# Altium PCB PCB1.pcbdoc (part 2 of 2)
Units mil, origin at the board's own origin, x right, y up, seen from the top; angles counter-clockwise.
Board outline 2362.2 x 2361.9 mil, 2 copper layers (Top Layer, Bottom Layer), stack 62.2 mil thick; 39 components, 38 nets, 262 pads, 86 vias.
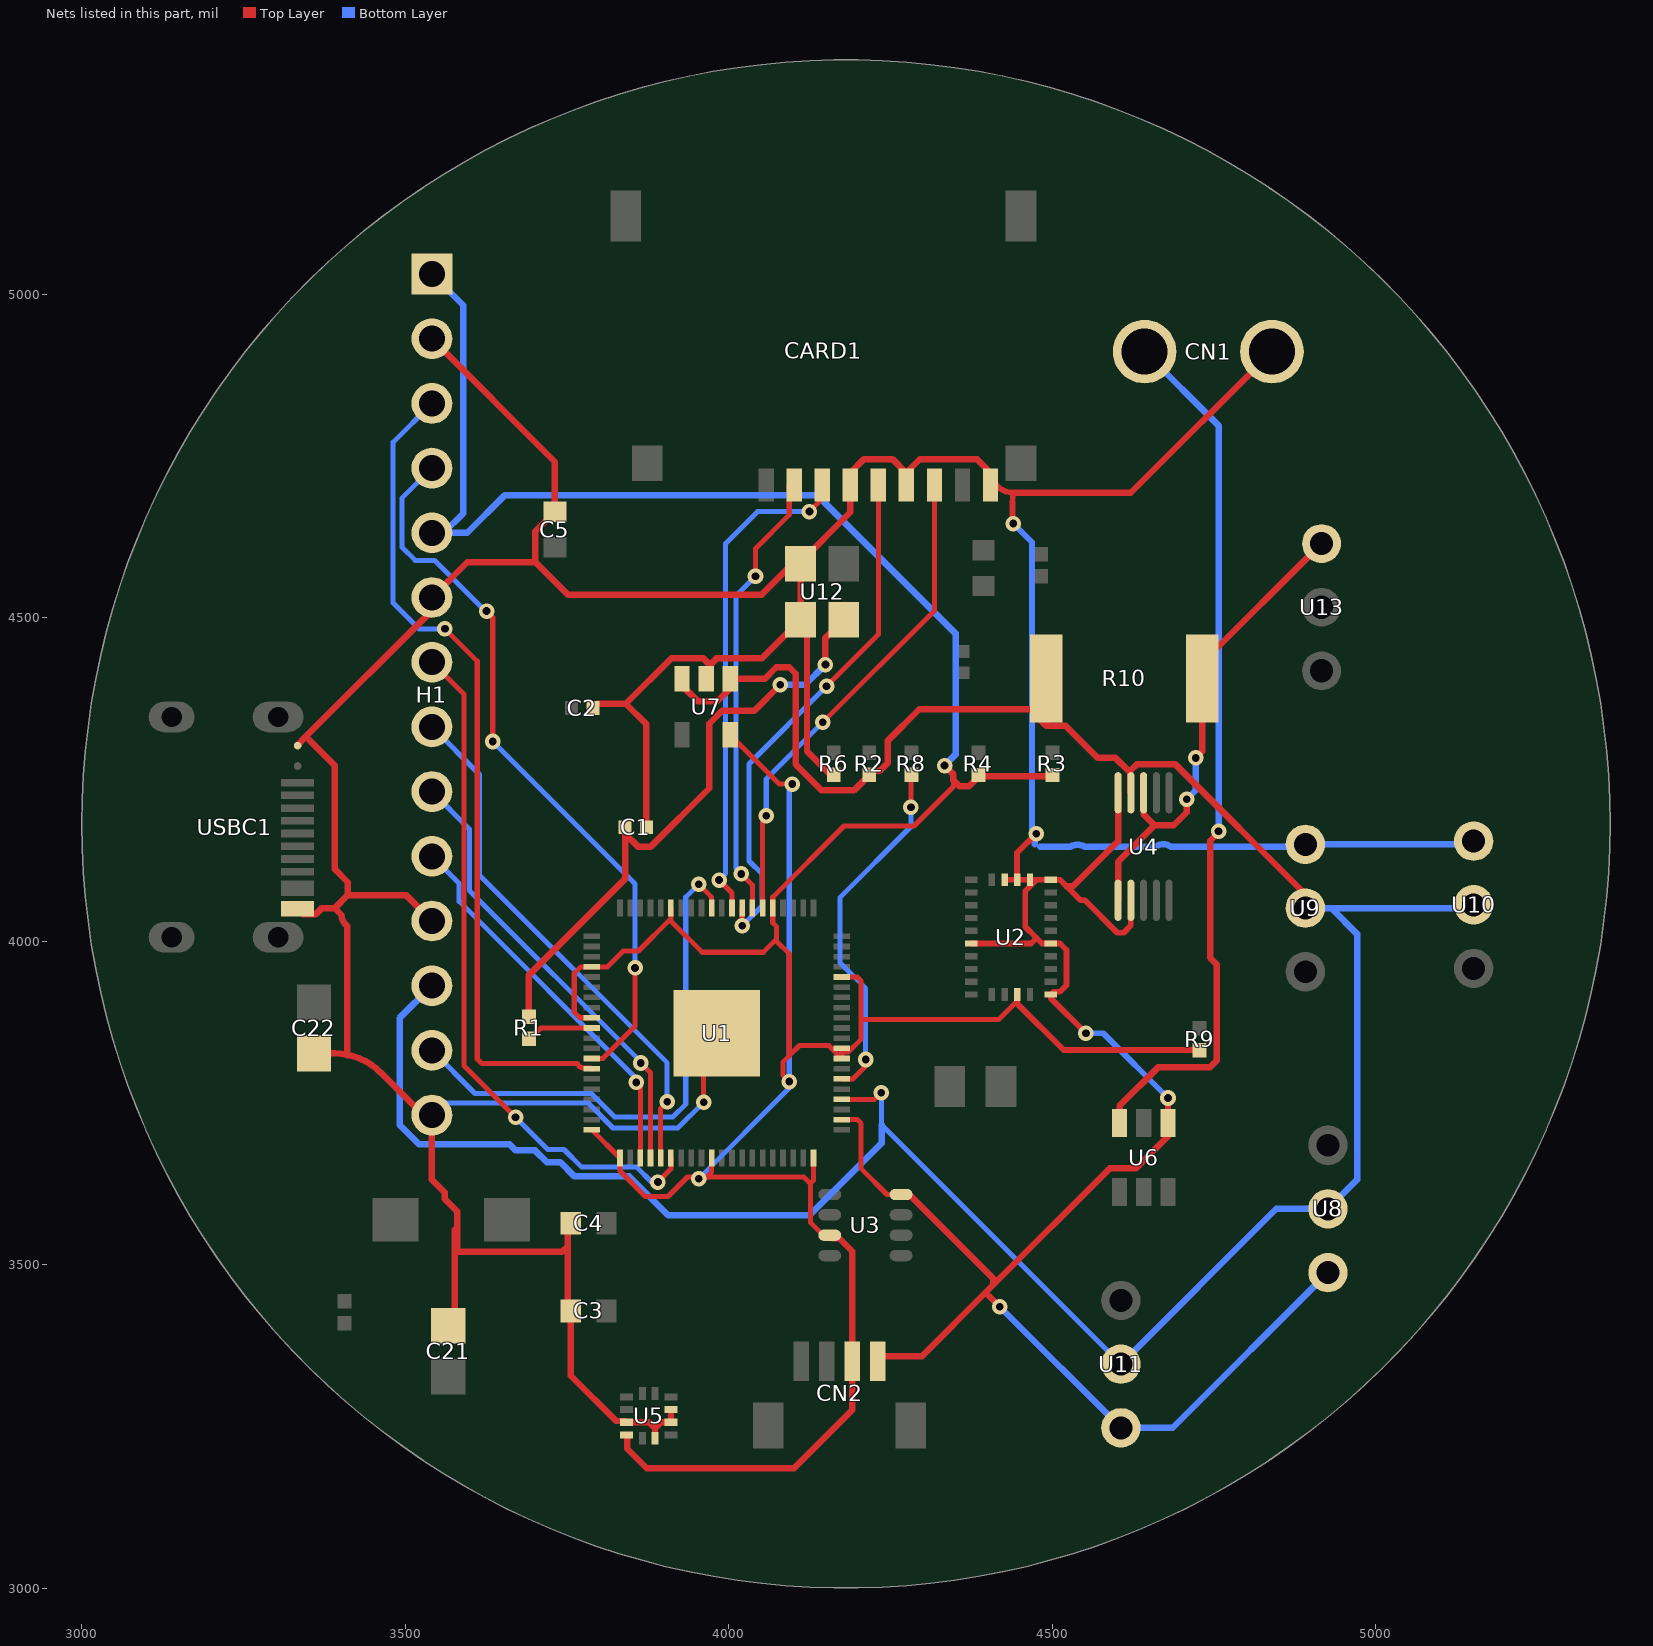
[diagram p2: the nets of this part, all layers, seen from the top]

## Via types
v1: diameter 24, hole 12, Top Layer to Bottom Layer, 86 vias

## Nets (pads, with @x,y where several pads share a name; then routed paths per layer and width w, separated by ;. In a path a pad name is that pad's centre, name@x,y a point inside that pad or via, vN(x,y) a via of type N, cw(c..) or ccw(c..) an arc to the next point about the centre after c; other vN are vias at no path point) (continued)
$1N398: H1.3 U1.34 | length 1298.7
  Top Layer w7.8: v1(3561.1,4482.7) 3611.1,4432.7 3611.1,3817.9 3618.5,3810.5 3765.8,3810.5 ; 3765.79,3810.47 ccw(c3775,3814.1) 3775,3804.2 3786.6,3804.2 U1.34@3788.1,3802.7
  Bottom Layer w7.8: H1.3@3541.1,4831.1 3481.1,4771.1 3481.1,4522.7 3521.1,4482.7 v1(3561.1,4482.7)
$1N399: H1.4 U1.33 | length 1137.2
  Top Layer w7.8: v1(3625.5,4510.1) 3635.1,4500.5 v1(3635.1,4308.5) ; U1.33@3788.1,3818.5 3805.1,3818.5 3855.1,3868.5 v1(3855.1,3958.5)
  Bottom Layer w7.8: H1.4@3541.1,4731.1 3495.1,4685.1 3495.1,4608.5 3515.1,4588.5 3545.1,4588.5 3623.5,4510.1 v1(3625.5,4510.1) ; v1(3635.1,4308.5) 3855.1,4088.5 v1(3855.1,3958.5)
$1N400: H1.7 U1.46 | length 1063.8
  Top Layer w7.8: H1.7@3541.1,4431.1 3590.4,4381.8 3590.4,3807.6 v1(3670.4,3727.6) ; v1(3890.4,3627.6) 3910.4,3647.6 U1.46@3910.4,3664.6
  Bottom Layer w7.8: v1(3670.4,3727.6) 3720.1,3678 3745.1,3678 3772,3651.1 3857,3651.1 3880.4,3627.6 v1(3890.4,3627.6)
$1N401: H1.8 U1.45 | length 821.3
  Top Layer w7.8: U1.45@3894.7,3664.6 3894.7,3741.6 v1(3904.7,3751.6)
  Bottom Layer w7.8: H1.8@3541.1,4331.1 3614.7,4257.5 3614.7,4101.8 3904.7,3811.8 v1(3904.7,3751.6)
$1N402: H1.9 U1.44 | length 706.4
  Top Layer w7.8: v1(3863.9,3811.6) 3878.9,3796.6 U1.44@3878.9,3664.6
  Bottom Layer w7.8: H1.9@3541.1,4231.1 3598.9,4173.3 3598.9,4078.3 3863.9,3813.3 v1(3863.9,3811.6)
$1N403: H1.10 U1.43 | length 599.9
  Top Layer w7.8: v1(3857,3781.6) 3863.2,3775.5 U1.43@3863.2,3664.6
  Bottom Layer w7.8: H1.10@3541.1,4131.1 3583.2,4089 3583.2,4061.4 3857,3787.5 v1(3857,3781.6)
$1N404: H1.13 U1.11 | length 836.8
  Top Layer w7.8: v1(3953.4,4088) 3973.4,4068 U1.11@3973.4,4051.1
  Bottom Layer w7.8: H1.13@3541.1,3831.1 3607.7,3764.6 3787.2,3764.6 3823.7,3728 3913.4,3728 3933.4,3748 3933.4,4068 v1(3953.4,4088)
$1N405: CARD1.5 U1.8 | length 820.4
  Top Layer w7.8: v1(4020.7,4023.9) U1.8@4020.7,4051.1 ; v1(4151.1,4393.9) 4231.1,4473.9 CARD1.5@4231.1,4713.4
  Bottom Layer w7.8: v1(4020.7,4023.9) 4051.1,4054.4 4051.1,4103.9 4031.1,4123.9 4031.1,4273.9 v1(4151.1,4393.9)
$1N406: CARD1.3 U1.9 | length 783.6
  Top Layer w7.8: v1(3984.9,4094.3) 4004.9,4074.3 U1.9@4004.9,4051.1 ; v1(4124.5,4663.9) 4144.5,4683.9 CARD1.3@4144.5,4713.4
  Bottom Layer w7.8: v1(3984.9,4094.3) 3994.9,4104.3 3994.9,4614.3 4044.5,4663.9 v1(4124.5,4663.9)
$1N409: CARD1.2 U1.7 | length 710
  Top Layer w7.8: v1(4019.3,4103.9) 4036.4,4086.7 U1.7@4036.4,4051.1 ; v1(4041.2,4563.9) 4041.2,4606.6 4093.4,4658.8 4093.4,4705.6 CARD1.2@4101.2,4713.4
  Bottom Layer w7.8: v1(4019.3,4103.9) 4011.2,4111.9 4011.2,4533.9 v1(4041.2,4563.9)
$1N410: CARD1.7 U1.6 | length 772.3
  Top Layer w7.8: U1.6@4052.2,4051.1 4052.2,4188.3 v1(4057.8,4193.9) ; v1(4145.3,4338.2) 4317.8,4510.6 CARD1.7@4317.8,4713.4
  Bottom Layer w7.8: v1(4057.8,4193.9) 4057.8,4250.6 v1(4145.3,4338.2)
$1N413: R8.1 U1.66 | length 557.5
  Top Layer w7.8: U1.66@4174.5,3787 4191.5,3787 4211.5,3807 v1(4211.5,3817) ; v1(4281.5,4207) 4281.5,4256.2 R8.1@4282.2,4256.8
  Bottom Layer w7.8: v1(4211.5,3817) 4211.5,3927 4171.5,3967 4171.5,4067 4281.5,4177 v1(4281.5,4207)
$1N418: CN1.2 U6.3 | length 1358.4
  Top Layer w10: U6.3@4604,3718.6 4604,3745.3 4664,3805.3 4744,3805.3 4754,3815.3 4754,3964 4744,3974 4744,4155.3 4757,4168.3 v1(4757,4169.9)
  Bottom Layer w10: CN1.2@4642.7,4911.1 4757,4796.8 v1(4757,4169.9)
$1N424: R1.1 U1.30 | length 103.9
  Top Layer w7.8: R1.1@3691.1,3849.1 3704.1,3862.1 3705.8,3862.1 3709.4,3865.7 U1.30@3788.1,3865.7
$1N425: C1.1 R1.2 U12.1 | length 928.8
  Top Layer w10: R1.2@3691.1,3883.1 3691.1,3947.6 3839.6,4096.1 C1.1@3839.6,4166.1 ; C1.1@3839.6,4176.1 C1.1@3839.6,4166.1 ; v1(4079.6,4396.1) 4039.6,4356.1 3989.6,4356.1 3969.6,4336.1 3969.6,4236.1 3879.6,4146.1 3859.6,4146.1 C1.1@3839.6,4166.1 ; v1(4149.3,4427.4) 4149.3,4468.5 U12.1@4177.7,4496.9
  Bottom Layer w10: v1(4079.6,4396.1) 4117.9,4396.1 v1(4149.3,4427.4)
$1N426: C1.2 C2.2 C3.2 C4.2 C5.2 C21.2 C22.2 CARD1.4 CARD1.6 CARD1.9 CN1.1 CN2.1 H1.2 H1.6 H1.11 H1.14 R6.2 U1.62 U1.81 U2.6 U2.10 U2.15 U2.16 U2.17 U2.18 U2.25 U3.5 U4.2 U4.10 U5.2 U5.3 U5.9 U5.12 U6.1 U7.2 U8.3 U9.3 U10.3 U11.3 U12.3 U12.4 USBC1.A1B12 USBC1.B1A12 | length 9984
  Top Layer w7.8: v1(3961.1,3751.1) 3961.1,3837.6 U1.81@3981.3,3857.8 ; U1.62@4174.5,3724 4199,3724 4204.6,3718.3 4204.6,3648.3 4244.6,3608.3 U3.5@4266.2,3608.3
  Top Layer w8.9: U2.25@4374.6,3996.3 4467.2,3996.3 4475.6,4004.7 ; CARD1.9@4409.9,4708.4 CARD1.9@4415.3,4703 ; CARD1.9@4415.19,4702.99 ccw(c4438.1,4725.9) 4438.1,4693.5 ; U2.18@4427.25,4094.75 ccw(c4428.1,4095.6) U2.18@4428.1,4094.4 ; U2.18@4428.1,4094.3 4440.1,4094.7 ; 4438.3,4679.5 4438.3,4646.8 v1(4439.7,4645.4) ; 4438.7,4684.2 4438.7,4692.8 ; U2.17@4445.5,4100 4445.5,4136.4 v1(4475.1,4166) ; U2.17@4445.9,4094.7 U2.16@4465.6,4094.7 4475.6,4094.7 ; v1(4551.9,3857.5) 4497.6,3911.8 U2.6@4497.6,3917.5 4501.9,3921.8 4511.9,3921.8 4521.9,3931.8 4521.9,3986.3 4511.9,3996.3 U2.10@4497.6,3996.3 4484,3996.3 4475.6,4004.7 ; U4.2@4621.4,4063 4621.4,4024.2 4610.3,4013 4600.3,4013 4550.3,4063 4543.6,4063 4521.9,4084.7 4511.9,4094.7 U2.15@4497.6,4094.7 4475.6,4094.7 ; U6.1@4678.8,3718.6 v1(4678.8,3757.5) ; 4475.6,4004.7 4458.3,4022.1 4458.3,4077.3 4475.6,4094.7
  Top Layer w9.9: C3.2@3755.9,3428.3 3755.9,3328.3 3825.9,3258.3 3839.6,3258.3 U5.9@3841.7,3256.3 3876.5,3256.3 3885.9,3246.8 ; U5.12@3885.9,3231.7 3885.9,3246.8 ; U5.3@3910.6,3275.9 U5.2@3910.6,3256.3 3895.4,3256.3 3885.9,3246.8 ; CN2.1@4230.2,3350.8 4238,3358.6 4298.8,3358.6 4398.8,3458.6 4408.8,3468.6 4588.8,3648.6 4628.8,3648.6 4678.8,3698.6 U6.1@4678.8,3718.6
  Top Layer w10: USBC1.B1A12@3333.5,4050.1 3342.5,4041.1 3361.1,4041.1 3371.1,4051.1 3390.8,4051.1 ; USBC1.A1B12@3333.5,4302.1 3341.1,4311.1 3541.1,4511.1 H1.6@3541.1,4531.1 3595.7,4585.7 3701.1,4585.7 ; 3351.1,4311.1 3391.1,4271.1 3391.1,4111.1 3411.1,4091.1 3411.1,4071.1 ; C22.2@3368,3826.4 3390.8,3826.4 cw(c3390.8,3726.4) 3410.22,3824.5 cw(c3390.8,3726.4) 3461.51,3797.11 H1.14@3536,3722.6 ; 3390.5,4051.4 3390.8,4051.1 ; 3410.26,4023.23 cw(c3424.1,4041.6) 3401.11,4040.8 3390.8,4051.1 ; 3410.3,3823.6 3410.3,3824.5 3410.3,4023.2 ; H1.14@3541.1,3748.4 3541.1,3631.1 3560.7,3611.5 3560.7,3601.5 3579.9,3582.3 3579.9,3519.5 3742.1,3519.5 3751.1,3528.5 ; H1.11@3541.1,4031.1 3501.1,4071.1 3411.1,4071.1 ; H1.2@3541.1,4931.1 3731.1,4741.1 C5.2@3731.1,4663.7 3701.1,4633.7 3701.1,4585.7 ; C21.2@3566.1,3405.5 3576.1,3415.5 3576.1,3554.1 ; C3.2@3755.9,3428.3 3751.1,3433.1 3751.1,3528.5 ; C4.2@3755.9,3563.9 3751.1,3561.1 3751.1,3528.5 ; C2.2@3790,4360.2 3796.6,4366.9 3840.8,4366.9 ; C1.2@3872.6,4176.1 3872.6,4335 3840.8,4366.9 ; U7.2@3964.9,4405.2 3970.8,4411.1 3970.8,4426.9 ; U12.3@4100.8,4585.7 4050.8,4535.7 3751.1,4535.7 3701.1,4585.7 ; R6.2@4162.3,4256.8 4157.4,4256.8 4120.8,4293.5 4120.8,4493.5 U12.4@4110.8,4503.5 ; U3.5@4266.2,3608.3 4279,3608.3 4408.8,3478.6 4408.8,3468.6 ; CARD1.6@4274.4,4713.4 CARD1.6@4274.4,4723.4 ; 4398.8,3458.6 4398.8,3455 v1(4418.8,3435) ; CARD1.9@4404.4,4713.4 4404.4,4724 4383.7,4744.8 4295.2,4744.8 4274.4,4724 CARD1.6@4274.4,4723.4 ; 4438.7,4693 4621.4,4693 CN1.1@4839.5,4911.1 ; 4521.9,4084.7 4531.9,4084.7 4601.9,4154.7 U4.10@4601.9,4229 ; 3390.8,4051.1 3391.1,4051.1 3411.1,4071.1 ; 3840.8,4366.9 3910.8,4436.9 3960.8,4436.9 3970.8,4426.9 ; 3970.8,4426.9 3980.8,4436.9 4050.8,4436.9 U12.4@4110.8,4496.9 U12.4@4110.8,4503.5 ; U12.4@4110.8,4503.5 U12.3@4110.8,4583.5 4110.8,4585.7 4187.8,4662.8 4187.8,4724 4208.9,4745.1 4252.8,4745.1 CARD1.6@4274.4,4723.4
  Bottom Layer w7.8: H1.14@3541.1,3731.1 3559.6,3749.6 3782.7,3749.6 3821.1,3711.1 3921.1,3711.1 v1(3961.1,3751.1)
  Bottom Layer w8.9: v1(4439.7,4645.4) 4468.6,4616.5 4468.6,4172.6 v1(4475.1,4166) ; v1(4551.9,3857.5) 4578.8,3857.5 v1(4678.8,3757.5)
  Bottom Layer w10: v1(4418.8,3435) U11.3@4606.1,3247.7 4686.1,3247.7 U8.3@4926.1,3487.7 ; 4472.9,4149.6 4472.9,4163.8 v1(4475.1,4166) ; 4481,4145.5 4527.2,4145.5 ; 4527.22,4145.56 cw(c4539,4125.8) 4550.78,4145.56 ; 4550.7,4145.5 4658.5,4145.5 ; 4658.54,4145.5 cw(c4671.5,4126.5) 4684.46,4145.5 ; 4684.4,4145.5 U9.3@4887.3,4145.5 ; U9.3@4891.1,4149.5 5146.1,4149.5 U10.3@5151.1,4154.5
$1N433: CN2.2 H1.1 H1.5 R3.2 R4.2 R9.2 U1.5 U1.15 U1.24 U1.29 U1.40 U1.41 U1.50 U1.60 U1.68 U1.69 U1.76 U2.4 U3.2 U5.10 U7.5 | length 5859.6
  Top Layer w7.8: U1.40@3788.1,3708.2 U1.41@3831.7,3664.6 3831.7,3644.6 3871,3605.4 3906,3605.4 3936,3635.4 3966,3635.4 ; U1.29@3788.1,3881.5 3769.8,3881.5 3761.1,3890.2 3761.1,3950.2 3771.1,3960.2 U1.24@3788.1,3960.2 3812.4,3960.2 3836.8,3984.6 3860.4,3984.6 3909.6,4033.7 ; U1.15@3910.4,4051.1 3910.4,4034.6 3909.6,4033.7 ; v1(3953.4,3632.8) 3963.4,3632.8 3966,3635.4 ; U1.50@3973.4,3664.6 3973.4,3642.8 3966,3635.4 ; U7.5@4002.3,4318.6 4078.1,4242.8 v1(4098.1,4242.8) ; v1(4093.4,3782.8) 4083.4,3792.8 4083.4,3812.8 4093.4,3822.8 ; U1.60@4130.9,3664.6 4130.9,3630.3 4126,3625.4 ; U3.2@4156,3545.4 4146,3545.4 4126,3565.4 4126,3625.4 ; U1.69@4174.5,3834.2 4174.5,3828.5 ; U1.76@4174.5,3944.5 4198.5,3944.5 4204.5,3938.5 4204.5,3878.5 ; 4347.1,4248.8 4347.1,4238.8 4286.3,4178 4177.9,4178 4067.9,4068 U1.5@4067.9,4051.1 4067.9,4028.3 4073.4,4022.8 4073.4,4002.8 ; 4445.9,3907.5 4416.9,3878.5 4204.5,3878.5 ; 3909.6,4033.7 3909.6,4031.9 3958.7,3982.8 4053.4,3982.8 4073.4,4002.8 ; 3966,3635.4 4116,3635.4 4126,3625.4 ; 4073.4,4002.8 4073.4,4000.3 4093.4,3980.3 4093.4,3822.8 ; 4093.4,3822.8 4109.1,3838.5 4154.5,3838.5 U1.68@4174.5,3818.5 4174.5,3828.5 ; 4174.5,3828.5 4184.5,3828.5 4204.5,3848.5 4204.5,3878.5
  Top Layer w8.9: U2.4@4445.9,3917.5 4445.9,3907.5 4445.9,3903.3 4517.7,3831.5 R9.2@4727.5,3831.5
  Top Layer w9.9: U5.10@3841.7,3236.6 3842.9,3235.3 3842.9,3215.3 3872.9,3185.3 4100.8,3185.3 4190.8,3275.3 CN2.2@4190.8,3350.8
  Top Layer w10: U3.2@4156,3545.4 4160.5,3540.8 4170.8,3540.8 4190.8,3520.8 CN2.2@4190.8,3350.8 ; v1(4333.4,4271.3) 4347.1,4257.6 4347.1,4248.8 4356.8,4239.1 4371,4239.1 4386.8,4254.9 R3.2@4495.8,4254.9 ; R3.2@4495.8,4255 ccw(c4495.8,4261) R3.2@4500.04,4256.76
  Bottom Layer w7.8: v1(3953.4,3632.8) 4093.4,3772.8 v1(4093.4,3782.8) 4093.4,4238.1 v1(4098.1,4242.8)
  Bottom Layer w10: H1.5@3541.1,4631.1 H1.5@3559.4,4631.1 ; H1.1@3541.1,5031.1 3589.4,4982.8 3589.4,4661.1 H1.5@3559.4,4631.1 ; v1(4333.4,4271.3) 4350.5,4288.3 4350.5,4475.5 4137.1,4688.8 3653.4,4688.8 3595.7,4631.1 H1.5@3559.4,4631.1
$1N435: R10.1 U4.1 U4.8 U13.1 | length 756.3
  Top Layer w10: U4.1@4601.7,4063 4601.7,4123 4657.9,4179.2 ; U4.8@4641.1,4229.2 4641.1,4196 4657.9,4179.2 ; v1(4707.9,4219.2) 4707.9,4199.2 4687.9,4179.2 4657.9,4179.2 ; v1(4721.8,4283.1) 4731.8,4293.1 R10.1@4731.8,4406.1 4731.8,4430.2 U13.1@4916.1,4614.5
  Bottom Layer w10: v1(4707.9,4219.2) 4721.8,4233.1 v1(4721.8,4283.1)
$1N436: H1.12 R2.2 R10.2 U1.64 U4.9 U7.1 U7.3 U8.2 U9.2 U10.2 U11.2 | length 4435.6
  Top Layer w7.8: U1.64@4174.5,3755.5 4225.5,3755.5 v1(4235.5,3765.5)
  Top Layer w10: U7.3@3927.5,4405.2 3932.3,4400.5 3932.3,4390.6 3952.3,4370.6 3982.3,4370.6 4002.3,4390.6 U7.1@4002.3,4405.2 4055.6,4405.2 4073.5,4423.1 4093.5,4423.1 4103.5,4413.1 4103.5,4273.1 4143.6,4232.9 4193.3,4232.9 4223.5,4263.1 4233.5,4263.1 4245.9,4275.5 4245.9,4309.9 4294.5,4358.5 4465,4358.5 4490.4,4333.1 ; R10.2@4490.4,4406.1 4490.4,4333.1 ; U4.9@4621.4,4229.2 4620.4,4230.2 4620.4,4263.1 ; U9.2@4891.1,4051.1 4891.1,4072.3 4690.4,4273.1 4630.4,4273.1 4620.4,4263.1 ; 4490.4,4333.1 4520.1,4333.1 4570.1,4283.1 4597.6,4283.1 4617.6,4263.1 4620.4,4263.1
  Bottom Layer w7.8: v1(4235.5,3765.5) 4236.1,3764.9 4236.1,3716.1 U11.2@4606.1,3346.1
  Bottom Layer w10: H1.12@3541.1,3931.1 3491.1,3881.1 3491.1,3716.1 3521.1,3686.1 3661.1,3686.1 3670.7,3676.5 3700.5,3676.5 3718.9,3658.1 3739.7,3658.1 3761.6,3636.2 3846,3636.2 3906.1,3576.1 4124.8,3576.1 4236.1,3687.4 4236.1,3716.1 ; U11.2@4606.1,3346.1 4846.1,3586.1 U8.2@4926.1,3586.1 4971.1,3631.2 4971.1,4011.1 4931.1,4051.1 ; U9.2@4891.1,4051.1 4931.1,4051.1 ; U10.2@5151.1,4056.1 5146.1,4051.1 4931.1,4051.1
pads on no net: CARD1.1 CARD1.8 CARD1.10 CARD1.11 CARD1.12 CARD1.13 CN2.0 U1.3 U1.4 U1.12 U1.13 U1.14 U1.16 U1.17 U1.18 U1.19 U1.20 U1.21 U1.22 U1.23 U1.25 U1.26 U1.27 U1.28 U1.35 U1.36 U1.37 U1.38 U1.39 U1.42 U1.47 U1.48 U1.49 U1.52 U1.53 U1.54 U1.55 U1.56 U1.57 U1.58 U1.59 U1.70 U1.71 U1.72 U1.73 U1.74 U1.75 U2.1 U2.2 U2.3 U2.5 U2.7 U2.8 U2.9 U2.12 U2.13 U2.14 U2.21 U2.22 U2.23 U2.24 U2.26 U2.27 U2.28 U3.1 U3.6 U3.7 U3.8 U4.3 U4.6 U4.7 U5.4 U5.5 U5.6 U5.7 U5.8 U7.4 U13.3 USBC1.1 USBC1.2 USBC1.3 USBC1.4 USBC1.A5 USBC1.A7 USBC1.B5 USBC1.B6 USBC1.B7 USBC1.B8

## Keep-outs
Board Outline Layer:
  region: 3328.4,4762.6 3328,4755.8 3326.8,4749 3324.9,4742.4 3322.2,4736.1 3318.8,4730.2 3314.8,4724.6 3310.2,4719.6 3305,4715.1 3299.3,4711.2 3293.2,4708 3286.9,4705.5 3280.2,4703.8 3273.4,4702.8 3266.6,4702.6 3259.8,4703.2 3253,4704.6 3246.5,4706.7 3240.3,4709.5 3234.4,4713.1 3229,4717.2 3224.1,4722 3219.7,4727.3 3216,4733.1 3213,4739.3 3210.7,4745.7 3209.1,4752.4 3208.4,4759.2 3208.4,4766.1 3209.1,4772.9 3210.7,4779.5 3213,4786 3216,4792.2 3219.7,4797.9 3224.1,4803.2 3229,4808 3234.4,4812.2 3240.3,4815.7 3246.5,4818.6 3253,4820.7 3259.8,4822.1 3266.6,4822.6 3273.4,4822.4 3280.2,4821.5 3286.9,4819.7 3293.2,4817.2 3299.3,4814 3305,4810.2 3310.2,4805.7 3314.8,4800.6 3318.8,4795.1 3322.2,4789.1 3324.9,4782.8 3326.8,4776.2 3328,4769.5
  region: 3328.4,4762.6 3328,4755.8 3326.8,4749 3324.9,4742.4 3322.2,4736.1 3318.8,4730.2 3314.8,4724.6 3310.2,4719.6 3305,4715.1 3299.3,4711.2 3293.2,4708 3286.9,4705.5 3280.2,4703.8 3273.4,4702.8 3266.6,4702.6 3259.8,4703.2 3253,4704.6 3246.5,4706.7 3240.3,4709.5 3234.4,4713.1 3229,4717.2 3224.1,4722 3219.7,4727.3 3216,4733.1 3213,4739.3 3210.7,4745.7 3209.1,4752.4 3208.4,4759.2 3208.4,4766.1 3209.1,4772.9 3210.7,4779.5 3213,4786 3216,4792.2 3219.7,4797.9 3224.1,4803.2 3229,4808 3234.4,4812.2 3240.3,4815.7 3246.5,4818.6 3253,4820.7 3259.8,4822.1 3266.6,4822.6 3273.4,4822.4 3280.2,4821.5 3286.9,4819.7 3293.2,4817.2 3299.3,4814 3305,4810.2 3310.2,4805.7 3314.8,4800.6 3318.8,4795.1 3322.2,4789.1 3324.9,4782.8 3326.8,4776.2 3328,4769.5
  region: 5159.3,4782 5158.9,4775.1 5157.7,4768.4 5155.8,4761.8 5153.1,4755.5 5149.8,4749.5 5145.7,4744 5141.1,4738.9 5135.9,4734.4 5130.3,4730.6 5124.2,4727.4 5117.8,4724.9 5111.2,4723.1 5104.4,4722.2 5097.5,4722 5090.7,4722.5 5084,4723.9 5077.5,4726 5071.2,4728.9 5065.4,4732.4 5059.9,4736.6 5055,4741.4 5050.7,4746.7 5047,4752.4 5043.9,4758.6 5041.6,4765.1 5040.1,4771.7 5039.3,4778.5 5039.3,4785.4 5040.1,4792.2 5041.6,4798.9 5043.9,4805.3 5047,4811.5 5050.7,4817.3 5055,4822.6 5059.9,4827.4 5065.4,4831.5 5071.2,4835.1 5077.5,4837.9 5084,4840 5090.7,4841.4 5097.5,4842 5104.4,4841.8 5111.2,4840.8 5117.8,4839.1 5124.2,4836.6 5130.3,4833.4 5135.9,4829.5 5141.1,4825 5145.7,4820 5149.8,4814.4 5153.1,4808.5 5155.8,4802.2 5157.7,4795.6 5158.9,4788.8
  region: 5159.3,4782 5158.9,4775.1 5157.7,4768.4 5155.8,4761.8 5153.1,4755.5 5149.8,4749.5 5145.7,4744 5141.1,4738.9 5135.9,4734.4 5130.3,4730.6 5124.2,4727.4 5117.8,4724.9 5111.2,4723.1 5104.4,4722.2 5097.5,4722 5090.7,4722.5 5084,4723.9 5077.5,4726 5071.2,4728.9 5065.4,4732.4 5059.9,4736.6 5055,4741.4 5050.7,4746.7 5047,4752.4 5043.9,4758.6 5041.6,4765.1 5040.1,4771.7 5039.3,4778.5 5039.3,4785.4 5040.1,4792.2 5041.6,4798.9 5043.9,4805.3 5047,4811.5 5050.7,4817.3 5055,4822.6 5059.9,4827.4 5065.4,4831.5 5071.2,4835.1 5077.5,4837.9 5084,4840 5090.7,4841.4 5097.5,4842 5104.4,4841.8 5111.2,4840.8 5117.8,4839.1 5124.2,4836.6 5130.3,4833.4 5135.9,4829.5 5141.1,4825 5145.7,4820 5149.8,4814.4 5153.1,4808.5 5155.8,4802.2 5157.7,4795.6 5158.9,4788.8
  region: 3336.6,3602.4 3336.2,3595.6 3335,3588.8 3333.1,3582.3 3330.4,3575.9 3327,3570 3323,3564.4 3318.4,3559.4 3313.2,3554.9 3307.5,3551 3301.5,3547.8 3295.1,3545.3 3288.5,3543.6 3281.7,3542.6 3274.8,3542.4 3268,3543 3261.3,3544.4 3254.8,3546.5 3248.5,3549.3 3242.6,3552.9 3237.2,3557.1 3232.3,3561.8 3228,3567.1 3224.3,3572.9 3221.2,3579.1 3218.9,3585.5 3217.4,3592.2 3216.6,3599 3216.6,3605.9 3217.4,3612.7 3218.9,3619.4 3221.2,3625.8 3224.3,3632 3228,3637.7 3232.3,3643 3237.2,3647.8 3242.6,3652 3248.5,3655.5 3254.8,3658.4 3261.3,3660.5 3268,3661.9 3274.8,3662.5 3281.7,3662.3 3288.5,3661.3 3295.1,3659.5 3301.5,3657.1 3307.5,3653.9 3313.2,3650 3318.4,3645.5 3323,3640.4 3327,3634.9 3330.4,3628.9 3333.1,3622.6 3335,3616 3336.2,3609.3
  region: 3336.6,3602.4 3336.2,3595.6 3335,3588.8 3333.1,3582.3 3330.4,3575.9 3327,3570 3323,3564.4 3318.4,3559.4 3313.2,3554.9 3307.5,3551 3301.5,3547.8 3295.1,3545.3 3288.5,3543.6 3281.7,3542.6 3274.8,3542.4 3268,3543 3261.3,3544.4 3254.8,3546.5 3248.5,3549.3 3242.6,3552.9 3237.2,3557.1 3232.3,3561.8 3228,3567.1 3224.3,3572.9 3221.2,3579.1 3218.9,3585.5 3217.4,3592.2 3216.6,3599 3216.6,3605.9 3217.4,3612.7 3218.9,3619.4 3221.2,3625.8 3224.3,3632 3228,3637.7 3232.3,3643 3237.2,3647.8 3242.6,3652 3248.5,3655.5 3254.8,3658.4 3261.3,3660.5 3268,3661.9 3274.8,3662.5 3281.7,3662.3 3288.5,3661.3 3295.1,3659.5 3301.5,3657.1 3307.5,3653.9 3313.2,3650 3318.4,3645.5 3323,3640.4 3327,3634.9 3330.4,3628.9 3333.1,3622.6 3335,3616 3336.2,3609.3
  region: 5167.5,3621.8 5167.1,3614.9 5166,3608.2 5164,3601.6 5161.4,3595.3 5158,3589.3 5154,3583.8 5149.3,3578.7 5144.1,3574.2 5138.5,3570.4 5132.4,3567.2 5126,3564.7 5119.4,3562.9 5112.6,3562 5105.8,3561.8 5098.9,3562.4 5092.2,3563.7 5085.7,3565.8 5079.5,3568.7 5073.6,3572.2 5068.2,3576.4 5063.2,3581.2 5058.9,3586.5 5055.2,3592.3 5052.2,3598.4 5049.9,3604.9 5048.3,3611.5 5047.5,3618.4 5047.5,3625.2 5048.3,3632 5049.9,3638.7 5052.2,3645.2 5055.2,3651.3 5058.9,3657.1 5063.2,3662.4 5068.2,3667.2 5073.6,3671.3 5079.5,3674.9 5085.7,3677.7 5092.2,3679.9 5098.9,3681.2 5105.8,3681.8 5112.6,3681.6 5119.4,3680.6 5126,3678.9 5132.4,3676.4 5138.5,3673.2 5144.1,3669.3 5149.3,3664.8 5154,3659.8 5158,3654.2 5161.4,3648.3 5164,3642 5166,3635.4 5167.1,3628.6
  region: 5167.5,3621.8 5167.1,3614.9 5166,3608.2 5164,3601.6 5161.4,3595.3 5158,3589.3 5154,3583.8 5149.3,3578.7 5144.1,3574.2 5138.5,3570.4 5132.4,3567.2 5126,3564.7 5119.4,3562.9 5112.6,3562 5105.8,3561.8 5098.9,3562.4 5092.2,3563.7 5085.7,3565.8 5079.5,3568.7 5073.6,3572.2 5068.2,3576.4 5063.2,3581.2 5058.9,3586.5 5055.2,3592.3 5052.2,3598.4 5049.9,3604.9 5048.3,3611.5 5047.5,3618.4 5047.5,3625.2 5048.3,3632 5049.9,3638.7 5052.2,3645.2 5055.2,3651.3 5058.9,3657.1 5063.2,3662.4 5068.2,3667.2 5073.6,3671.3 5079.5,3674.9 5085.7,3677.7 5092.2,3679.9 5098.9,3681.2 5105.8,3681.8 5112.6,3681.6 5119.4,3680.6 5126,3678.9 5132.4,3676.4 5138.5,3673.2 5144.1,3669.3 5149.3,3664.8 5154,3659.8 5158,3654.2 5161.4,3648.3 5164,3642 5166,3635.4 5167.1,3628.6
  lines w0.1: 3208.4,4759.2 3209.1,4752.4 3210.7,4745.7 3213,4739.3 3216,4733.1 3219.7,4727.3 3224.1,4722 3229,4717.2 3234.4,4713.1 3240.3,4709.5 3246.5,4706.7 3253,4704.6 3259.8,4703.2 3266.6,4702.6 3273.4,4702.8 3280.2,4703.8 3286.9,4705.5 3293.2,4708 3299.3,4711.2 3305,4715.1 3310.2,4719.6 3314.8,4724.6 3318.8,4730.2 3322.2,4736.1 3324.9,4742.4 3326.8,4749 3328,4755.8 3328.4,4762.6 3328,4769.5 3326.8,4776.2 3324.9,4782.8 3322.2,4789.1 3318.8,4795.1 3314.8,4800.6 3310.2,4805.7 3305,4810.2 3299.3,4814 3293.2,4817.2 3286.9,4819.7 3280.2,4821.5 3273.4,4822.4 3266.6,4822.6 3259.8,4822.1 3253,4820.7 3246.5,4818.6 3240.3,4815.7 3234.4,4812.2 3229,4808 3224.1,4803.2 3219.7,4797.9 3216,4792.2 3213,4786 3210.7,4779.5 3209.1,4772.9 3208.4,4766.1 3208.4,4759.2 ; 3216.6,3599 3217.4,3592.2 3218.9,3585.5 3221.2,3579.1 3224.3,3572.9 3228,3567.1 3232.3,3561.8 3237.2,3557.1 3242.6,3552.9 3248.5,3549.3 3254.8,3546.5 3261.3,3544.4 3268,3543 3274.8,3542.4 3281.7,3542.6 3288.5,3543.6 3295.1,3545.3 3301.5,3547.8 3307.5,3551 3313.2,3554.9 3318.4,3559.4 3323,3564.4 3327,3570 3330.4,3575.9 3333.1,3582.3 3335,3588.8 3336.2,3595.6 3336.6,3602.4 3336.2,3609.3 3335,3616 3333.1,3622.6 3330.4,3628.9 3327,3634.9 3323,3640.4 3318.4,3645.5 3313.2,3650 3307.5,3653.9 3301.5,3657.1 3295.1,3659.5 3288.5,3661.3 3281.7,3662.3 3274.8,3662.5 3268,3661.9 3261.3,3660.5 3254.8,3658.4 3248.5,3655.5 3242.6,3652 3237.2,3647.8 3232.3,3643 3228,3637.7 3224.3,3632 3221.2,3625.8 3218.9,3619.4 3217.4,3612.7 3216.6,3605.9 3216.6,3599 ; 5039.3,4778.5 5040.1,4771.7 5041.6,4765.1 5043.9,4758.6 5047,4752.4 5050.7,4746.7 5055,4741.4 5059.9,4736.6 5065.4,4732.4 5071.2,4728.9 5077.5,4726 5084,4723.9 5090.7,4722.5 5097.5,4722 5104.4,4722.2 5111.2,4723.1 5117.8,4724.9 5124.2,4727.4 5130.3,4730.6 5135.9,4734.4 5141.1,4738.9 5145.7,4744 5149.8,4749.5 5153.1,4755.5 5155.8,4761.8 5157.7,4768.4 5158.9,4775.1 5159.3,4782 5158.9,4788.8 5157.7,4795.6 5155.8,4802.2 5153.1,4808.5 5149.8,4814.4 5145.7,4820 5141.1,4825 5135.9,4829.5 5130.3,4833.4 5124.2,4836.6 5117.8,4839.1 5111.2,4840.8 5104.4,4841.8 5097.5,4842 5090.7,4841.4 5084,4840 5077.5,4837.9 5071.2,4835.1 5065.4,4831.5 5059.9,4827.4 5055,4822.6 5050.7,4817.3 5047,4811.5 5043.9,4805.3 5041.6,4798.9 5040.1,4792.2 5039.3,4785.4 5039.3,4778.5 ; 5047.5,3618.4 5048.3,3611.5 5049.9,3604.9 5052.2,3598.4 5055.2,3592.3 5058.9,3586.5 5063.2,3581.2 5068.2,3576.4 5073.6,3572.2 5079.5,3568.7 5085.7,3565.8 5092.2,3563.7 5098.9,3562.4 5105.8,3561.8 5112.6,3562 5119.4,3562.9 5126,3564.7 5132.4,3567.2 5138.5,3570.4 5144.1,3574.2 5149.3,3578.7 5154,3583.8 5158,3589.3 5161.4,3595.3 5164,3601.6 5166,3608.2 5167.1,3614.9 5167.5,3621.8 5167.1,3628.6 5166,3635.4 5164,3642 5161.4,3648.3 5158,3654.2 5154,3659.8 5149.3,3664.8 5144.1,3669.3 5138.5,3673.2 5132.4,3676.4 5126,3678.9 5119.4,3680.6 5112.6,3681.6 5105.8,3681.8 5098.9,3681.2 5092.2,3679.9 5085.7,3677.7 5079.5,3674.9 5073.6,3671.3 5068.2,3667.2 5063.2,3662.4 5058.9,3657.1 5055.2,3651.3 5052.2,3645.2 5049.9,3638.7 5048.3,3632 5047.5,3625.2 5047.5,3618.4
  lines w10: 3000,4181.1 3000.4,4150.4 3001.6,4119.8 3003.6,4089.2 3006.4,4058.7 3009.9,4028.2 3014.3,3997.9 3019.5,3967.6 3025.4,3937.5 3032.1,3907.6 3039.6,3877.9 3047.8,3848.3 3056.9,3819 3066.6,3790 3077.2,3761.2 3088.4,3732.7 3100.5,3704.4 3113.2,3676.5 3126.7,3649 3140.8,3621.8 3155.7,3595 3171.3,3568.6 3187.5,3542.6 3204.4,3517 3222,3491.8 3240.2,3467.2 3259,3443 3278.5,3419.3 3298.6,3396.1 3319.3,3373.5 3340.5,3351.4 3362.4,3329.8 3384.7,3308.9 3407.6,3288.5 3431.1,3268.7 3455,3249.5 3479.4,3231 3504.3,3213.1 3529.7,3195.9 3555.5,3179.3 3581.7,3163.4 3608.3,3148.2 3635.4,3133.6 3662.7,3119.8 3690.5,3106.7 3718.5,3094.4 3746.9,3082.7 3775.5,3071.8 3804.5,3061.7 3833.7,3052.3 3863.1,3043.6 3892.7,3035.7 3922.6,3028.6 3952.6,3022.3 3982.7,3016.8 4013,3012 4043.4,3008.1 4073.9,3004.9 4104.5,3002.5 4135.1,3000.9 4165.8,3000.1 4196.4,3000.1 4227.1,3000.9 4257.7,3002.5 4288.3,3004.9 4318.8,3008.1 4349.2,3012 4379.5,3016.8 4409.6,3022.3 4439.6,3028.6 4469.5,3035.7 4499.1,3043.6 4528.5,3052.3 4557.7,3061.7 4586.7,3071.8 4615.3,3082.7 4643.7,3094.4 4671.8,3106.7 4699.5,3119.8 4726.9,3133.6 4753.9,3148.2 4780.5,3163.4 4806.7,3179.3 4832.5,3195.9 4857.9,3213.1 4882.8,3231 4907.2,3249.5 4931.1,3268.7 4954.6,3288.5 4977.5,3308.9 4999.8,3329.8 5021.7,3351.4 5042.9,3373.5 5063.6,3396.1 5083.7,3419.3 5103.2,3443 5122,3467.2 5140.2,3491.8 5157.8,3517 5174.7,3542.6 5191,3568.6 5206.5,3595 5221.4,3621.8 5235.6,3649 5249,3676.5 5261.7,3704.4 5273.8,3732.7 5285,3761.2 5295.6,3790 5305.3,3819 5314.4,3848.3 5322.6,3877.9 5330.1,3907.6 5336.8,3937.5 5342.8,3967.6 5347.9,3997.9 5352.3,4028.2 5355.8,4058.7 5358.6,4089.2 5360.6,4119.8 5361.8,4150.4 5362.2,4181.1 5361.8,4211.8 5360.6,4242.4 5358.6,4273 5355.8,4303.5 5352.3,4334 5347.9,4364.4 5342.8,4394.6 5336.8,4424.7 5330.1,4454.6 5322.6,4484.3 5314.4,4513.9 5305.3,4543.2 5295.6,4572.2 5285,4601 5273.8,4629.5 5261.7,4657.8 5249,4685.7 5235.6,4713.2 5221.4,4740.4 5206.5,4767.2 5191,4793.6 5174.7,4819.7 5157.8,4845.2 5140.2,4870.4 5122,4895 5103.2,4919.2 5083.7,4942.9 5063.6,4966.1 5042.9,4988.7 5021.7,5010.8 4999.8,5032.4 4977.5,5053.3 4954.6,5073.7 4931.1,5093.5 4907.2,5112.7 4882.8,5131.2 4857.9,5149.1 4832.5,5166.3 4806.7,5182.9 4780.5,5198.8 4753.9,5214 4726.9,5228.6 4699.5,5242.4 4671.8,5255.5 4643.7,5267.8 4615.3,5279.5 4586.7,5290.4 4557.7,5300.5 4528.5,5309.9 4499.1,5318.6 4469.5,5326.5 4439.6,5333.6 4409.6,5339.9 4379.5,5345.4 4349.2,5350.2 4318.8,5354.2 4288.3,5357.3 4257.7,5359.7 4227.1,5361.3 4196.4,5362.1 4165.8,5362.1 4135.1,5361.3 4104.5,5359.7 4073.9,5357.3 4043.4,5354.2 4013,5350.2 3982.7,5345.4 3952.6,5339.9 3922.6,5333.6 3892.7,5326.5 3863.1,5318.6 3833.7,5309.9 3804.5,5300.5 3775.5,5290.4 3746.9,5279.5 3718.5,5267.8 3690.5,5255.5 3662.7,5242.4 3635.4,5228.6 3608.3,5214 3581.7,5198.8 3555.5,5182.9 3529.7,5166.3 3504.3,5149.1 3479.4,5131.2 3455,5112.7 3431.1,5093.5 3407.6,5073.7 3384.7,5053.3 3362.4,5032.4 3340.5,5010.8 3319.3,4988.7 3298.6,4966.1 3278.5,4942.9 3259,4919.2 3240.2,4895 3222,4870.4 3204.4,4845.2 3187.5,4819.7 3171.3,4793.6 3155.7,4767.2 3140.8,4740.4 3126.7,4713.2 3113.2,4685.7 3100.5,4657.8 3088.4,4629.5 3077.2,4601 3066.6,4572.2 3056.9,4543.2 3047.8,4513.9 3039.6,4484.3 3032.1,4454.6 3025.4,4424.7 3019.5,4394.6 3014.3,4364.4 3009.9,4334 3006.4,4303.5 3003.6,4273 3001.6,4242.4 3000.4,4211.8 3000,4181.1

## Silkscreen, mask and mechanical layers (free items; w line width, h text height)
Top Silkscreen Layer:
  drawing of 309 lines, arcs and shapes, not listed
  text "WYVERN-E r7.4" at 3445,4431.2 h70.9 r90
Mechanical Layer:
  drawing of 220 lines, arcs and shapes, not listed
